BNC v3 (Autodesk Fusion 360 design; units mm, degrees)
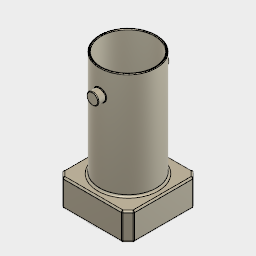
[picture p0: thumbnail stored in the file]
sketch "Sketch1" plane through (0, 0, 0) normal (0, 1, 0) x axis (1, 0, 0)
  line L1 (-6, 6) -> (6, 6)
  line L2 (-6, -6) -> (-6, 6)
  line L3 (6, -6) -> (-6, -6)
  line L4 (6, 6) -> (6, -6)
extrude "Extrude1" new body sketch "Sketch1" along normal blind 4.6
cylinder_primitive "CylinderPrimitive1" Height 17.9 Diameter 9.6
chamfer "Chamfer1" distance 1
chamfer "Chamfer2" distance 1
chamfer "Chamfer3" distance 1
chamfer "Chamfer4" distance 1
cylinder_primitive "CylinderPrimitive2" Height 20 Diameter 2
move "Move1"
move_face "MoveFace1"
move_face "MoveFace2"
hole "Hole1" HoleDepth 18 HoleDiameter 9 TipAngle 118
fillet "Fillet1" radius 0.3
fillet "Fillet2" radius 0.25
fillet "Fillet3" radius 0.25
fillet "Fillet4" radius 0.25
fillet "Fillet5" radius 0.25
fillet "Fillet6" radius 0.1
fillet "Fillet7" radius 0.1
fillet "Fillet8" radius 0.1
combine "Combine1"
combine "Combine2"
fillet "Fillet9" radius 0.1
fillet "Fillet10" radius 0.1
